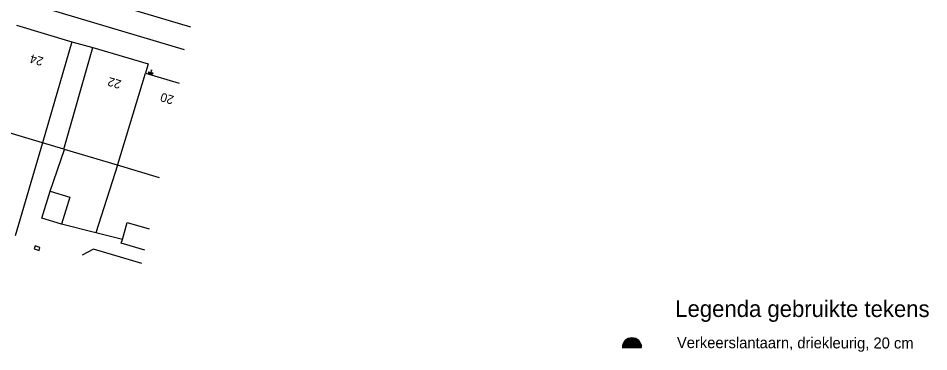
# Model space of a CAD drawing. Extents: x 81065 to 81486, y 452384 to 452681.
# Drawn here: x 81331.8 to 81414.5, y 452473.4 to 452503.7 of the extents above; entities that cross this region are included whole.
import ezdxf

# ---------------------------------------------------------------- set-up
doc = ezdxf.new("R2010")
doc.units = 0
for name, color, linetype in [('B-BH-AL-TOPOGRAFIE_HUISNUMMER-T25', 7, 'Continuous'), ('B-BH-KL-DATA_CAI_KAST-S', 7, 'Continuous'), ('B-BH-OG-TERREIN_ERF-GV', 7, 'Continuous'), ('B-BH-OG-TOPOGRAFIE_BEBOUWING-GV', 7, 'Continuous'), ('B-BH-OG-TOPOGRAFIE_BEBOUWING_PANDSCHEIDING-GV', 7, 'Continuous'), ('B-BH-VH-KANTOPSLUITING-GV', 7, 'Continuous'), ('B-SRI-KOLK_COMBINATIE-S', 7, 'Continuous'), ('X-XX-AL-TEKENBLAD_VERKLARING-T70', 7, 'Continuous')]:
    doc.layers.add(name, color=color, linetype=linetype)

msp = doc.modelspace()

# ---------------------------------------------------------------- linework, layer by layer
at = {"layer": 'B-BH-KL-DATA_CAI_KAST-S'}
for p, q in [((81343.651, 452498.64), (81343.694, 452498.783)), ((81343.987, 452498.539), (81343.651, 452498.64)), ((81343.676, 452498.659), (81343.705, 452498.754)), ((81343.676, 452498.659), (81343.976, 452498.568)), ((81343.694, 452498.783), (81344.03, 452498.682)), ((81343.701, 452498.677), (81343.715, 452498.725)), ((81343.701, 452498.677), (81343.966, 452498.597)), ((81343.705, 452498.754), (81344.005, 452498.663)), ((81343.715, 452498.725), (81343.98, 452498.645)), ((81343.726, 452498.696), (81343.956, 452498.626)), ((81343.861, 452498.97), (81343.993, 452498.93)), ((81343.928, 452498.95), (81343.862, 452498.732)), ((81343.98, 452498.645), (81343.966, 452498.597)), ((81344.005, 452498.663), (81343.976, 452498.568)), ((81344.03, 452498.682), (81343.987, 452498.539))]:
    msp.add_line(p, q, dxfattribs=at)
at = {"layer": 'B-BH-OG-TERREIN_ERF-GV'}
msp.add_line((81340.834, 452490.298), (81338.883, 452484.161), dxfattribs=at)
at = {"layer": 'B-BH-OG-TOPOGRAFIE_BEBOUWING-GV'}
for p, q in [((81331.67, 452503.013), (81336.689, 452501.516)), ((81336.689, 452501.516), (81334.029, 452492.346)), ((81335.959, 452491.755), (81334.029, 452492.346))]:
    msp.add_line(p, q, dxfattribs=at)
for points in [[(81334.029, 452492.346), (81315.022, 452498.014), (81310.179, 452499.459), (81307.134, 452500.366), (81305.843, 452499.661), (81297.632, 452495.182)], [(81336.017, 452491.737), (81335.959, 452491.755), (81338.584, 452500.98), (81343.626, 452499.502), (81343.364, 452498.661), (81346.42, 452497.758)], [(81344.657, 452489.172), (81340.834, 452490.298), (81336.017, 452491.737)], [(81335.764, 452484.94), (81333.97, 452485.49), (81334.721, 452487.942)], [(81334.721, 452487.942), (81336.516, 452487.392), (81335.764, 452484.94)], [(81341.28, 452483.563), (81341.728, 452485.108), (81343.704, 452484.534)], [(81343.308, 452482.606), (81341.181, 452483.223), (81341.28, 452483.563)]]:
    msp.add_lwpolyline(points, dxfattribs=at)
at = {"layer": 'B-BH-OG-TOPOGRAFIE_BEBOUWING_PANDSCHEIDING-GV'}
msp.add_line((81340.849, 452490.293), (81343.364, 452498.661), dxfattribs=at)
at = {"layer": 'B-BH-VH-KANTOPSLUITING-GV'}
for p, q in [((81336.689, 452501.516), (81338.584, 452500.98)), ((81334.029, 452492.346), (81331.561, 452483.888)), ((81334.721, 452487.942), (81336.017, 452491.737)), ((81338.883, 452484.161), (81335.764, 452484.94)), ((81341.28, 452483.563), (81338.883, 452484.161)), ((81343.059, 452481.393), (81338.669, 452482.67))]:
    msp.add_line(p, q, dxfattribs=at)
for points in [[(81347.493, 452502.83), (81323.617, 452509.943)], [(81346.914, 452500.791), (81323.025, 452507.908)], [(81338.669, 452482.67), (81337.615, 452482.149)]]:
    msp.add_lwpolyline(points, dxfattribs=at)
at = {"layer": 'B-SRI-KOLK_COMBINATIE-S'}
for p, q in [((81333.375, 452482.983), (81333.286, 452482.702)), ((81333.802, 452482.849), (81333.375, 452482.983)), ((81333.713, 452482.567), (81333.802, 452482.849)), ((81333.286, 452482.702), (81333.713, 452482.567))]:
    msp.add_line(p, q, dxfattribs=at)
at = {"layer": 'X-XX-AL-TEKENBLAD_VERKLARING-T70'}
for p, q in [((81387.208, 452474.573), (81387.857, 452474.575)), ((81387.298, 452474.603), (81387.77, 452474.605)), ((81387.47, 452474.633), (81387.599, 452474.635)), ((81386.66, 452473.763), (81388.408, 452473.763)), ((81386.662, 452473.823), (81388.405, 452473.825)), ((81386.662, 452473.793), (81388.406, 452473.793)), ((81386.666, 452473.853), (81388.402, 452473.855)), ((81386.669, 452473.883), (81388.399, 452473.885)), ((81386.674, 452473.915), (81388.394, 452473.913)), ((81386.68, 452473.943), (81388.388, 452473.945)), ((81386.686, 452473.973), (81388.381, 452473.975)), ((81386.695, 452474.005), (81388.373, 452474.003)), ((81386.704, 452474.033), (81388.364, 452474.035)), ((81386.713, 452474.065), (81388.354, 452474.065)), ((81386.725, 452474.093), (81388.342, 452474.093)), ((81386.738, 452474.123), (81388.33, 452474.122)), ((81386.753, 452474.152), (81388.315, 452474.153)), ((81386.768, 452474.183), (81388.298, 452474.183)), ((81386.785, 452474.213), (81388.283, 452474.213)), ((81386.804, 452474.243), (81388.264, 452474.243)), ((81386.825, 452474.273), (81388.243, 452474.273)), ((81386.848, 452474.303), (81388.22, 452474.303)), ((81386.872, 452474.333), (81388.195, 452474.333)), ((81386.899, 452474.363), (81388.168, 452474.363)), ((81386.93, 452474.393), (81388.139, 452474.395)), ((81386.962, 452474.423), (81388.105, 452474.423)), ((81386.999, 452474.455), (81388.067, 452474.455)), ((81387.04, 452474.483), (81388.028, 452474.483)), ((81387.088, 452474.515), (81387.98, 452474.515)), ((81387.142, 452474.543), (81387.925, 452474.545))]:
    msp.add_line(p, q, dxfattribs=at)
msp.add_arc((81387.534, 452473.763), 0.873, 359.99975, 179.99975, dxfattribs=at)

# ---------------------------------------------------------------- texts
at = {"layer": 'B-BH-AL-TOPOGRAFIE_HUISNUMMER-T25'}
for s, p in [('24', (81334.176, 452500.065)), ('22', (81341.237, 452497.98)), ('20', (81346.017, 452496.57))]:
    msp.add_text(s, height=0.8, rotation=163.55353, dxfattribs=at).set_placement(p)
at = {"layer": 'X-XX-AL-TEKENBLAD_VERKLARING-T70'}
for s, height, rotation, p in [('Legenda gebruikte tekens', 1.5, 359.97961, (81391.465, 452476.529)), ('Verkeerslantaarn, driekleurig, 20 cm', 1, 359.86856, (81391.615, 452473.707))]:
    msp.add_text(s, height=height, rotation=rotation, dxfattribs=at).set_placement(p)

doc.saveas('drawing.dxf')
